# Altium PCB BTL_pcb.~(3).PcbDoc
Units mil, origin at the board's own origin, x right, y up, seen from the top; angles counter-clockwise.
Board outline 6000 x 4000 mil, 2 copper layers (Top Layer, Bottom Layer); 11 components, 6 nets, 26 pads, 0 vias.
Unrouted connection lines stored in the file: 20.
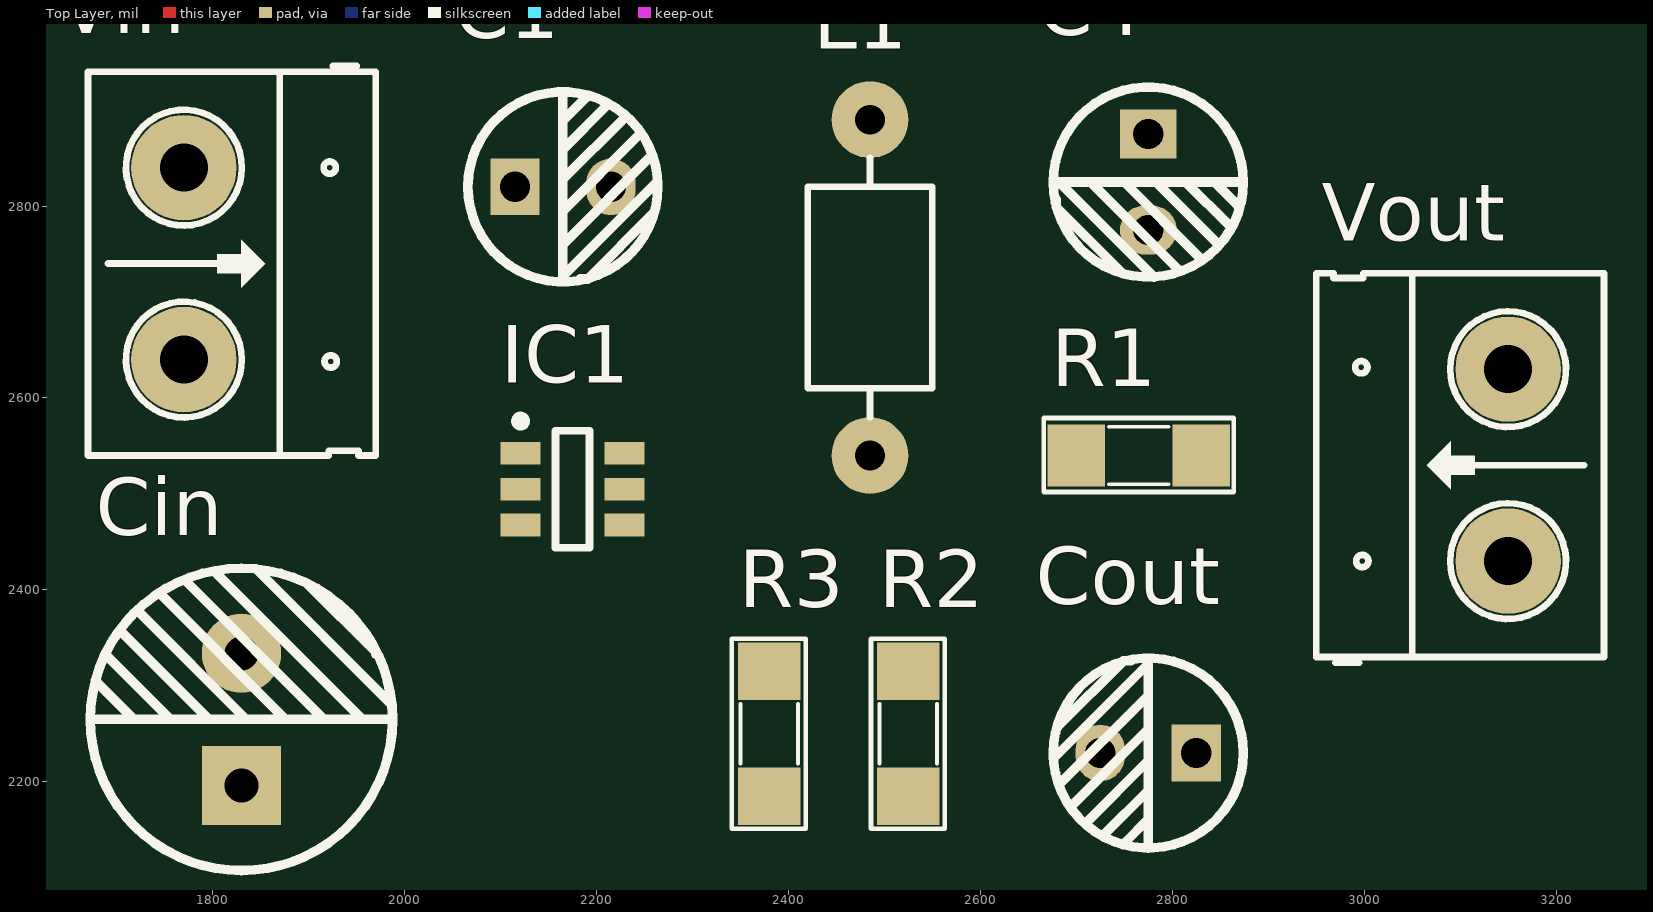
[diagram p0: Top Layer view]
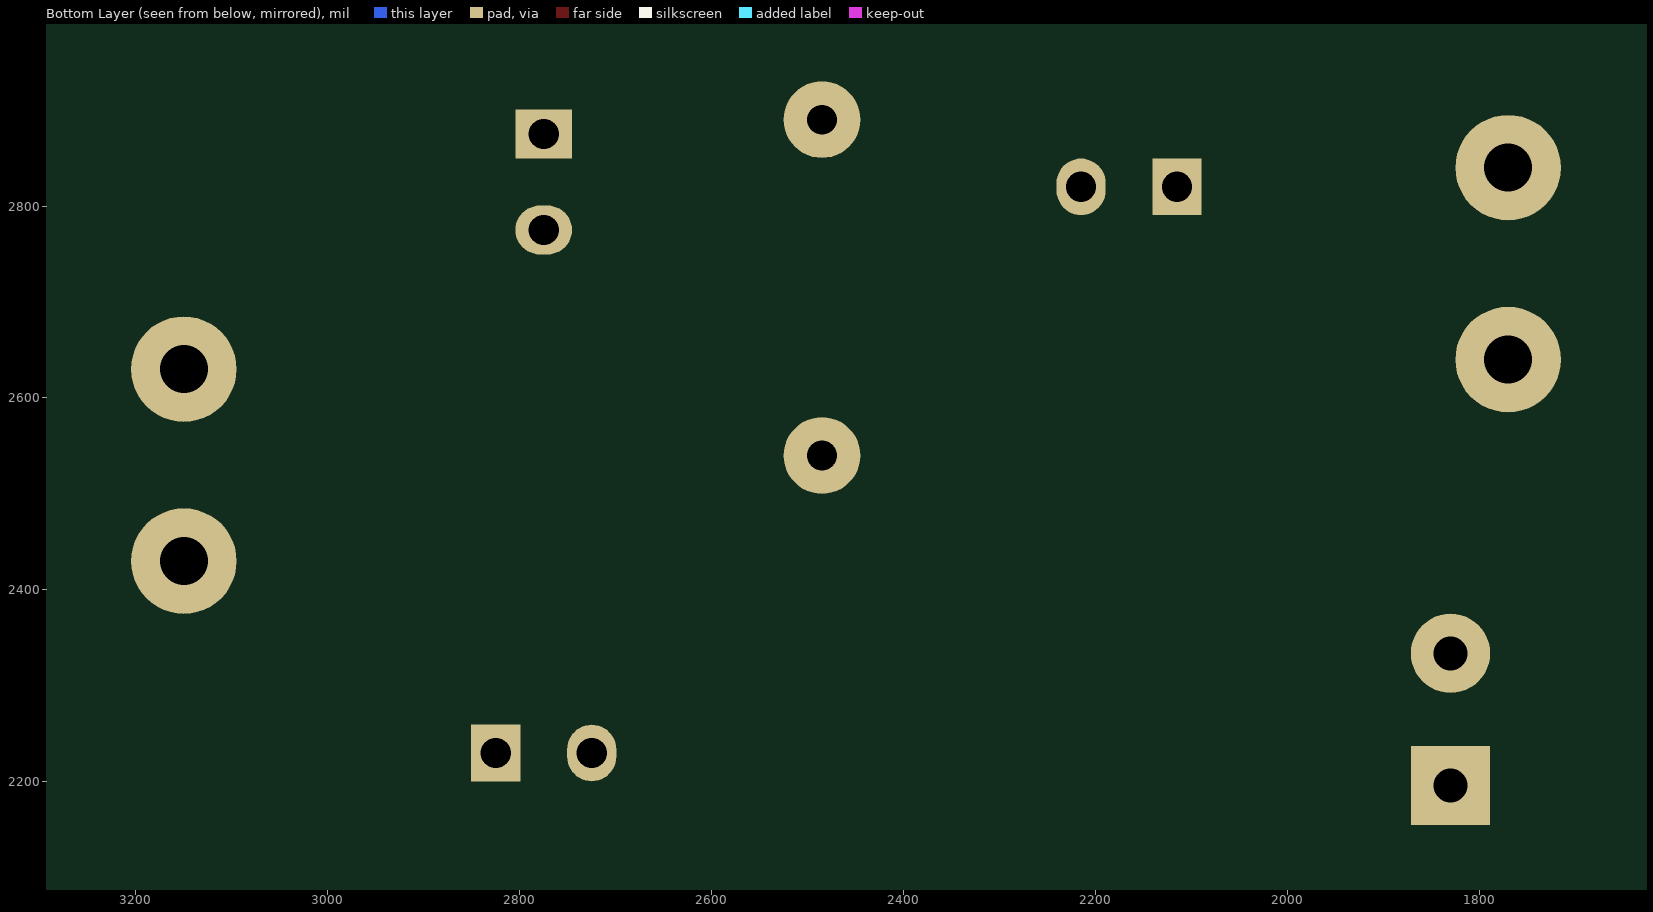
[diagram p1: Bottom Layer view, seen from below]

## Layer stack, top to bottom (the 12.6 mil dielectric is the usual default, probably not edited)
Top Solder: solder mask 0.4, Solder Resist, Dk 3.5
Top Layer: signal copper 1.4
Dielectric 1: dielectric 12.6, FR-4, Dk 4.8
Bottom Layer: signal copper 1.4
Bottom Solder: solder mask 0.4, Solder Resist, Dk 3.5

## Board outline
1000,1000 7000,1000 7000,5000 1000,5000

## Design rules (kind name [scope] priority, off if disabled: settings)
Clearance [All] p1: gap=10 ignorepadtopadclearanceinfootprint=FALSE except(0: Arc-Hole Track-Hole SMDPad-Hole THPad-Hole Via-Hole Fill-Hole Poly-Hole Region-Hole Text-Hole)
PolygonConnect [All] p1: connectstyle=Relief reliefconductorwidth=10 reliefentries=4 polygonreliefangle="90 Angle" airgapwidth=10
RoomDefinition BTL [InComponentClass('BTL')] p1: confinementstyle=ConfineIn formatcopy=TRUE lockcomponents=FALSE outline 7045,1060 10110,1060 10110,1610 7045,1610
RoutingVias [All] p1: holewidth=28 width=50 viastyle="Through Hole" minholewidth=28 minwidth=50 maxholewidth=28 maxwidth=50
SolderMaskExpansion [All] p1: expansion=4 istentingtop=FALSE
Width [All] p1: maxlimit=10 minlimit=10 preferedwidth=10
30 further rules are at their usual default settings.

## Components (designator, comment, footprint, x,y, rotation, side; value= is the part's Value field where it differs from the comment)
C1 "0.1uF" "tu hoa 5mm" 2165,2820 r0 top
C4 "22pF" "tu hoa 5mm" 2775,2825 r270 top
Cin "10uF" "tu hoa 8mm" 1830,2265 r90 top
Cout "22uF" "tu hoa 5mm" 2775,2230 r180 top
IC1 "SY8120B1ABC" SY8120B1ABC_SOT23 2175,2505 r0 top
L1 "4.7uH" L/0.4 2485,2540 r90 top value="150 mH"
R1 "100k" SM-RES-1206 2700,2540 r0 top value="R1/4W - 1K"
R2 "22.1k" SM-RES-1206 2525,2185 r90 top value="R1/4W - 1K"
R3 "1M" SM-RES-1206 2380,2185 r90 top value="R1/4W - 1K"
Vin "Header 2" HED2 1770,2840 r270 top
Vout "Header 2" HED2 3150,2430 r90 top

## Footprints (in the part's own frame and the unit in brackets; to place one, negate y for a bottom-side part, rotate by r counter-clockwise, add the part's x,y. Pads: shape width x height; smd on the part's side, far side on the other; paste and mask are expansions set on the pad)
HED2 [mil] "Header 2, 2 pin, hight 300mil, Pin to Pin 200, Colour Green"
  round 110 hole 50: 1(0,0) 2(200,0)
  silkscreen extent -106,-100 300,200, body extent -92,-140 302,155, height 394
L/0.4 [mil] "Inductor , 2 Pin, L 350mil, W 150 mil"
  round 80 hole 31: 1(0,0) 2(350,0)
  silkscreen extent 40,-65 310,65
SM-RES-1206 [mil]
  rect 60x65 smd: 1(0,0) 2(130,0)
  silkscreen extent -34,-38 164,39, body extent 2,-31 128,32, height 40
SY8120B1ABC_SOT23 [mm]
  rect 1.05x0.6 smd: 1(-1.375,0.95) 2(-1.375,0) 3(-1.375,-0.95) 4(1.375,-0.95) 5(1.375,0) 6(1.375,0.95)
  silkscreen extent -1.5,-1.55 0.45,1.92, body extent -1.37,-1.42 1.63,1.68, height 1.4
"tu hoa 5mm" [mm]
  rect 1.3x1.5 hole 0.8: 1(-1.27,0)
  oval 1.3x1.5 hole 0.8: 2(1.27,0)
  silkscreen extent -2.51,-2.51 2.51,2.51, body extent -3.12,-3.18 3.23,3.18, height 14.55
"tu hoa 8mm" [mm]
  rect 2.1x2.1 hole 0.9: 1(-1.75,0)
  round 2.1 hole 0.9: 2(1.75,0)
  silkscreen extent -4,-4 4,4, body extent -4.1,-4.07 4.1,4.13, height 13.81

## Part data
C1: library part "Tu Hoa 0.1uF 50V 5x11", "Cắm"
C4: library part "Tu Hoa 2.2uF 100V 5x11", "Cắm"
Cin: library part "Tu Hoa 4.7uF 400V 8x12", "Cắm"
Cout: library part "Tu Hoa 22uF 25V 5x11", "Cắm"
IC1: Package=None
L1: library part L1, "Inductor"
R1 R2 R3: library part R, "Resistor 1/4W"
Vin Vout: library part Hed2, "Header 2 (Green)"

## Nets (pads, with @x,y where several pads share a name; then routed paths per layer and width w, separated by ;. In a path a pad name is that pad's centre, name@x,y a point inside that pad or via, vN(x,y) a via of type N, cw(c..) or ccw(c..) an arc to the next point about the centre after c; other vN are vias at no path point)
GND: Cin.2 Cout.2 IC1.2 R2.1 R3.1 Vin.2 Vout.2
NetC1_1: C1.1 IC1.1
NetC1_2: C1.2 IC1.6 L1.1
NetC4_1: C4.1 Cout.1 L1.2 R1.2 Vout.1
NetC4_2: C4.2 IC1.3 R1.1 R2.2
NetCin_1: Cin.1 IC1.4 IC1.5 R3.2 Vin.1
